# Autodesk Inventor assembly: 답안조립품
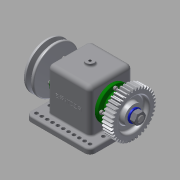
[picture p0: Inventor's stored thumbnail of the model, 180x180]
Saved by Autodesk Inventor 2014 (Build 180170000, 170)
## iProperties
Created: 2018-11
Part Number: 답안조립품
Document SubType Name: Assembly
Designer: kh
Author: kh
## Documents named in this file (13)
- C:\Users\kh\Desktop\481107V1016\답안조립품.iam
- C:\Users\kh\Desktop\481107V1016\본체.ipt
- C:\Users\kh\Desktop\481107V1016\V벨트풀리.ipt
- C:\Users\kh\Desktop\481107V1016\너트 M12x1.25.ipt
- C:\Users\kh\Desktop\481107V1016\베어링 6203.ipt
- C:\Users\kh\Desktop\481107V1016\볼트 M4.ipt
- C:\Users\kh\Desktop\481107V1016\부시.ipt
- C:\Users\kh\Desktop\481107V1016\스퍼기어.ipt
- C:\Users\kh\Desktop\481107V1016\오일 실 26 38 8.ipt
- C:\Users\kh\Desktop\481107V1016\와셔 12x24.ipt
- C:\Users\kh\Desktop\481107V1016\축.ipt
- C:\Users\kh\Desktop\481107V1016\커버.ipt
- C:\Users\kh\Desktop\481107V1016\키 5x5x12.ipt
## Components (1 placed, 1 different names)
1. V벨트풀리:1
